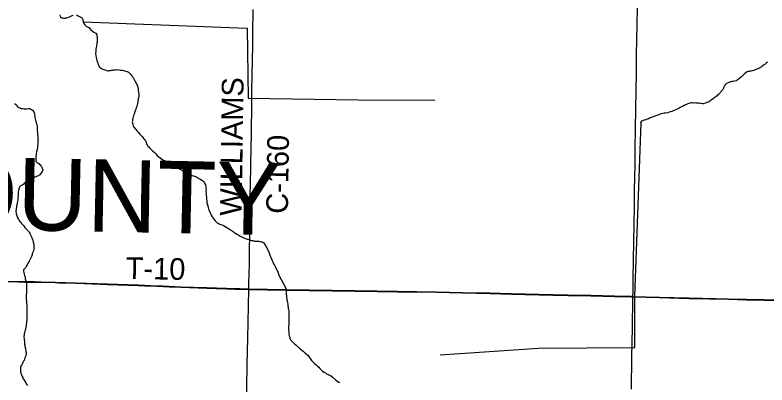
# Model space of a CAD drawing. Extents: x -483 to 680, y 0 to 440.
# Drawn here: x 243.8 to 342.2, y 111.5 to 160 of the extents above; entities that cross this region are included whole.
import ezdxf

# ---------------------------------------------------------------- set-up
doc = ezdxf.new("R2010")
doc.units = 0
for name, color, linetype in [('GM_X_County_Road', 7, 'Continuous'), ('GM_X_County_Road_Text', 7, 'Continuous'), ('GM_X_County_Text', 7, 'Continuous'), ('GM_X_Minor_River', 7, 'Continuous'), ('GM_X_State_Route', 7, 'Continuous'), ('GM_X_Township_Road', 7, 'Continuous'), ('GM_X_Township_Road_Text', 7, 'Continuous'), ('SH_Cut_Line', 7, 'Continuous')]:
    doc.layers.add(name, color=color, linetype=linetype)

msp = doc.modelspace()

# ---------------------------------------------------------------- linework, layer by layer
at = {"layer": 'GM_X_County_Road'}
for points in [[(274.37, 124.047), (274.394, 124.871), (274.43, 126.086), (274.446, 127.389), (274.474, 129.44), (274.494, 130.962), (274.509, 132.174), (274.533, 134.349), (274.567, 136.463), (274.596, 137.83), (274.632, 140.223), (274.683, 142.771), (274.707, 144.231), (274.724, 145.443), (274.751, 147.463), (274.786, 150.167), (274.846, 153.958), (274.889, 156.133), (274.909, 157.625), (274.962, 160.732)], [(273.399, 73.76), (273.41, 74.745), (273.48, 78.087), (273.533, 80.653), (273.585, 83.452), (273.663, 87.183), (273.754, 91.381), (273.896, 97.444), (273.926, 99.154), (273.943, 100.709), (273.972, 102.73), (273.986, 104.13), (274.036, 106.462), (274.073, 108.171), (274.125, 111.216), (274.177, 114.235), (274.24, 117.656), (274.34, 121.854), (274.37, 124.047)]]:
    msp.add_lwpolyline(points, dxfattribs=at)
at = {"layer": 'GM_X_Minor_River'}
for points in [[(249.628, 160.019), (249.679, 159.846), (249.732, 159.711), (249.902, 159.648), (249.996, 159.626), (250.129, 159.622), (250.224, 159.619), (250.338, 159.615), (250.472, 159.629), (250.568, 159.645), (250.762, 159.753), (250.973, 159.822), (251.264, 159.965), (251.399, 160.017)], [(251.799, 160.023), (251.968, 159.96), (252.287, 159.798), (252.473, 159.678), (252.566, 159.598), (252.635, 159.387), (252.67, 159.271), (252.703, 159.118)], [(252.703, 159.118), (274.156, 158.295), (274.281, 149.103), (288.694, 148.911)], [(252.703, 159.118), (252.791, 158.887), (252.899, 158.712), (253.029, 158.594), (253.14, 158.514), (253.234, 158.473), (253.422, 158.372), (253.679, 158.078), (254.069, 157.779), (254.331, 157.638), (254.457, 157.405), (254.472, 157.291), (254.508, 157.194), (254.503, 157.061), (254.516, 156.871), (254.529, 156.68), (254.521, 156.433), (254.478, 156.263), (254.453, 156.093), (254.429, 155.922), (254.404, 155.752), (254.359, 155.525), (254.331, 155.26), (254.322, 154.975), (254.332, 154.689), (254.381, 154.44), (254.432, 154.248), (254.483, 154.037), (254.553, 153.845), (254.623, 153.652), (254.693, 153.46), (254.801, 153.285), (254.91, 153.11), (255.041, 153.03), (255.172, 152.949), (255.379, 152.885), (255.529, 152.823), (255.661, 152.781), (255.774, 152.739), (255.869, 152.717), (255.983, 152.713), (256.098, 152.748), (256.251, 152.761), (256.404, 152.794), (256.557, 152.808), (256.691, 152.823), (256.844, 152.837), (257.015, 152.85), (257.206, 152.863), (257.396, 152.838), (257.585, 152.794), (257.794, 152.768), (257.983, 152.723), (258.549, 152.571), (258.643, 152.53), (258.772, 152.412), (258.845, 152.295), (258.955, 152.178), (259.047, 152.06), (259.12, 151.963), (259.248, 151.806), (259.338, 151.651), (259.41, 151.497), (259.499, 151.323), (259.589, 151.148), (259.661, 151.013), (259.733, 150.877), (259.787, 150.78), (259.82, 150.627), (259.871, 150.454), (259.9, 150.149), (259.948, 149.881), (259.959, 149.633), (259.971, 149.386), (259.945, 149.177), (259.902, 149.027), (259.879, 148.913), (259.855, 148.762), (259.831, 148.591), (259.787, 148.422), (259.743, 148.233), (259.699, 148.044), (259.636, 147.856), (259.613, 147.743), (259.551, 147.592), (259.49, 147.461), (259.448, 147.329), (259.406, 147.198), (259.362, 147.028), (259.299, 146.859), (259.256, 146.689), (259.211, 146.481), (259.167, 146.293), (259.143, 146.122), (259.12, 146.009), (259.135, 145.894), (259.132, 145.799), (259.185, 145.664), (259.237, 145.51), (259.327, 145.336), (259.638, 144.945)], [(342.286, 153.823), (342.113, 153.713), (342.016, 153.639), (341.919, 153.546), (341.822, 153.472), (341.725, 153.398), (341.551, 153.249), (341.435, 153.176), (341.3, 153.103), (341.204, 153.048), (341.05, 152.975), (340.896, 152.921), (340.666, 152.831), (340.493, 152.759), (340.32, 152.706), (340.148, 152.672), (339.976, 152.637), (339.824, 152.622), (339.709, 152.605), (339.613, 152.569), (339.517, 152.514), (339.381, 152.403), (339.303, 152.31), (339.186, 152.198), (339.031, 152.049), (338.876, 151.919), (338.663, 151.753), (338.507, 151.604), (338.391, 151.511), (338.276, 151.476), (338.16, 151.402), (337.95, 151.35), (337.796, 151.296), (337.643, 151.28), (337.51, 151.264), (337.395, 151.248), (337.3, 151.231), (337.126, 151.14), (337.011, 151.085), (336.915, 151.03), (336.798, 150.919), (336.719, 150.806), (336.641, 150.694), (336.581, 150.581), (336.521, 150.449), (336.422, 150.261), (336.305, 150.111), (336.227, 150.018), (336.109, 149.868), (336.031, 149.755), (335.895, 149.644), (335.798, 149.551), (335.681, 149.44), (335.545, 149.328), (335.429, 149.236), (335.333, 149.181), (335.217, 149.088), (334.926, 148.866), (334.791, 148.755), (334.636, 148.644), (334.386, 148.536), (334.137, 148.446), (333.907, 148.394), (333.754, 148.378), (333.603, 148.401), (333.508, 148.422), (333.356, 148.444), (333.166, 148.448), (333.014, 148.471), (332.881, 148.474), (332.71, 148.497), (332.557, 148.481), (332.424, 148.484), (332.272, 148.487), (332.138, 148.452), (332.004, 148.436), (331.851, 148.382), (331.677, 148.291), (331.37, 148.165), (331.158, 148.036), (330.946, 147.927), (330.734, 147.817), (330.542, 147.726), (330.349, 147.616), (330.157, 147.525)], [(288.694, 148.911), (298.75, 148.85)], [(243.678, 148.421), (243.827, 148.321), (243.919, 148.223), (244.029, 148.086), (244.14, 147.987), (244.271, 147.907), (244.421, 147.845), (244.571, 147.783), (244.704, 147.76), (244.799, 147.756), (244.969, 147.713), (245.083, 147.709), (245.216, 147.705), (245.37, 147.738), (245.579, 147.75), (245.713, 147.745), (245.844, 147.684), (245.937, 147.624), (246.05, 147.563), (246.251, 147.309), (246.285, 147.194), (246.32, 147.097), (246.334, 146.926), (246.347, 146.754), (246.38, 146.582), (246.413, 146.41), (246.445, 146.237), (246.478, 146.065), (246.53, 145.911), (246.563, 145.758), (246.615, 145.604), (246.648, 145.432), (246.679, 145.221), (246.669, 144.898), (246.698, 144.612), (246.727, 144.345), (246.739, 144.116), (246.75, 143.849), (246.763, 143.678), (246.779, 143.582), (246.773, 143.373), (246.745, 143.108), (246.719, 142.88), (246.691, 142.615), (246.645, 142.369), (246.578, 142.067), (246.552, 141.84), (246.528, 141.669), (246.503, 141.499), (246.499, 141.366), (246.476, 141.252)], [(330.157, 147.525), (329.946, 147.454), (329.754, 147.363), (329.562, 147.31), (329.39, 147.276), (329.217, 147.204), (328.95, 147.171), (328.759, 147.138), (328.567, 147.104), (328.376, 147.051), (328.223, 147.016), (328.069, 146.944), (327.916, 146.89), (327.781, 146.836), (327.647, 146.801), (327.551, 146.765), (327.417, 146.73), (327.283, 146.675), (327.186, 146.62), (327.071, 146.566), (326.937, 146.531), (326.687, 146.422), (326.533, 146.349), (326.361, 146.296), (326.131, 146.225), (325.997, 146.19), (325.862, 146.136), (325.766, 146.1), (325.707, 145.987), (325.686, 145.93), (325.707, 145.987), (325.686, 145.892)], [(325.686, 145.892), (324.886, 123.142)], [(259.638, 144.945), (259.767, 144.789), (259.913, 144.613), (260.097, 144.417), (260.245, 144.26), (260.392, 144.103), (260.52, 143.946), (260.649, 143.79), (260.758, 143.653), (260.831, 143.536), (260.885, 143.439), (260.938, 143.304), (260.99, 143.151), (261.062, 143.015), (261.151, 142.822), (261.318, 142.702), (261.428, 142.546), (261.594, 142.389), (261.779, 142.211), (261.983, 142.034), (262.186, 141.836), (262.388, 141.621), (262.592, 141.443), (262.759, 141.304), (262.945, 141.165), (263.131, 141.025), (263.412, 140.883), (263.637, 140.78), (263.824, 140.66), (264.01, 140.54), (264.217, 140.457), (264.423, 140.355), (264.685, 140.213), (264.966, 140.052), (265.284, 139.87), (265.546, 139.728), (265.807, 139.567), (266.01, 139.37), (266.273, 139.248), (266.479, 139.146), (266.705, 139.062), (266.932, 138.998), (267.14, 138.953), (267.271, 138.891), (267.384, 138.849), (267.496, 138.789), (267.646, 138.708), (267.795, 138.608), (267.945, 138.527), (268.114, 138.445), (268.319, 138.305), (268.465, 138.129), (268.557, 138.012), (268.629, 137.895), (268.719, 137.74), (268.751, 137.549), (268.767, 137.434), (268.763, 137.32), (268.776, 137.129), (268.769, 136.901), (268.779, 136.635), (268.79, 136.387), (268.821, 136.139), (268.832, 135.891), (268.863, 135.662), (268.892, 135.395), (268.96, 135.145), (269.045, 134.838), (269.114, 134.588), (269.183, 134.377), (269.272, 134.184), (269.361, 133.99), (269.45, 133.778), (269.577, 133.584), (269.723, 133.389), (269.85, 133.194), (269.978, 133.038), (270.107, 132.901), (270.218, 132.783), (270.349, 132.721), (270.48, 132.641), (270.592, 132.58), (270.724, 132.538), (270.856, 132.495), (270.969, 132.454), (271.063, 132.412), (271.157, 132.371), (271.344, 132.27), (271.456, 132.209), (271.624, 132.089), (271.773, 131.989), (271.922, 131.908), (272.053, 131.809), (272.183, 131.729), (272.332, 131.628), (272.463, 131.529), (272.911, 131.248), (273.06, 131.148), (273.246, 131.009), (273.547, 130.904), (273.81, 130.781)], [(246.476, 141.252), (246.473, 141.157), (246.486, 140.967), (246.502, 140.852), (246.63, 140.715), (246.761, 140.615), (246.872, 140.535), (246.983, 140.437), (247.076, 140.358), (247.149, 140.26), (247.222, 140.162), (247.276, 140.046), (247.346, 139.854), (247.417, 139.719), (247.356, 139.587), (247.315, 139.494), (247.254, 139.362), (247.115, 139.196), (247.035, 139.084), (246.919, 139.031), (246.822, 138.958), (246.667, 138.887), (246.513, 138.816), (246.377, 138.745), (246.222, 138.674), (246.048, 138.584), (245.875, 138.533), (245.74, 138.48), (245.625, 138.446), (245.509, 138.412), (245.413, 138.358), (245.235, 138.174), (245.118, 138.063), (244.979, 137.916), (244.862, 137.806), (244.745, 137.733), (244.591, 137.662), (244.494, 137.608), (244.377, 137.536), (244.295, 137.368), (244.273, 137.254), (244.25, 137.122), (244.227, 137.028), (244.184, 136.858), (244.178, 136.687), (244.175, 136.573), (244.171, 136.44), (244.166, 136.307), (244.14, 136.079), (244.133, 135.851), (244.105, 135.586), (244.059, 135.34), (244.015, 135.151), (243.973, 135.02), (243.948, 134.83), (243.921, 134.603), (243.899, 134.489), (243.894, 134.356), (243.891, 134.261), (243.904, 134.071), (243.938, 133.936), (243.989, 133.745), (244.058, 133.514), (244.165, 133.301), (244.258, 133.203), (244.329, 133.068), (244.402, 132.951), (244.512, 132.814), (244.622, 132.696), (244.715, 132.617), (244.825, 132.481), (244.917, 132.401), (245.062, 132.168), (245.246, 131.972), (245.614, 131.56), (245.706, 131.443), (245.758, 131.308), (245.829, 131.135), (245.918, 130.942), (245.989, 130.787), (246.041, 130.614), (246.111, 130.441), (246.162, 130.23), (246.211, 129.981), (246.222, 129.714), (246.233, 129.485), (246.208, 129.296), (246.165, 129.126), (246.124, 129.033), (246.082, 128.939), (246.06, 128.825), (246.019, 128.732), (245.995, 128.58), (245.93, 128.354), (245.789, 128.093), (245.606, 127.737), (245.404, 127.363), (245.282, 127.12), (245.122, 126.897), (245.004, 126.768), (244.885, 126.62)], [(273.81, 130.781), (274.035, 130.697), (274.204, 130.615), (274.336, 130.573), (274.449, 130.531), (274.581, 130.489), (274.733, 130.465), (274.884, 130.441), (275.016, 130.398), (275.13, 130.376), (275.282, 130.371), (275.415, 130.366), (275.568, 130.38), (275.681, 130.358), (275.814, 130.334), (275.984, 130.29), (276.116, 130.267), (276.285, 130.185), (276.396, 130.086), (276.45, 129.99), (276.521, 129.835), (276.631, 129.679), (276.719, 129.467), (276.899, 129.138), (277.023, 128.848), (277.127, 128.541), (277.251, 128.251), (277.374, 127.924), (277.499, 127.653), (277.625, 127.421), (277.732, 127.208), (277.876, 126.956), (278.02, 126.666), (278.18, 126.337), (278.32, 125.933), (279.243, 124.199)], [(244.885, 126.62), (244.898, 126.448), (244.911, 126.257), (244.943, 126.066), (244.995, 125.893), (245.048, 125.777), (245.082, 125.643), (245.097, 125.528), (245.113, 125.433), (245.275, 124.879)], [(245.275, 124.879), (245.284, 124.116), (245.264, 123.888), (245.264, 123.603), (245.244, 123.299), (245.244, 123.09), (245.243, 122.956), (245.243, 122.842), (245.243, 122.728), (245.262, 122.576), (245.261, 122.405), (245.28, 122.215), (245.299, 122.025), (245.298, 121.74), (245.298, 121.588), (245.298, 121.436), (245.297, 121.303), (245.297, 121.188), (245.297, 121.074), (245.297, 120.941), (245.297, 120.789), (245.315, 120.618), (245.315, 120.428), (245.315, 120.219), (245.256, 119.668), (245.237, 119.44), (245.218, 119.25), (245.198, 119.079), (245.16, 118.927), (245.141, 118.813), (245.103, 118.718), (245.083, 118.623), (245.026, 118.452), (244.988, 118.357), (244.969, 118.262), (244.949, 118.129), (244.949, 118.034), (244.93, 117.92), (244.93, 117.787), (244.949, 117.616), (244.967, 117.445), (244.986, 117.293), (245.005, 117.179), (245.004, 117.046), (245.023, 116.893), (245.042, 116.722), (245.061, 116.57), (245.098, 116.418), (245.117, 116.304), (245.155, 116.209), (245.174, 116.057), (245.193, 115.924), (245.211, 115.771), (245.211, 115.619), (245.173, 115.41), (245.134, 115.258), (245.096, 115.163), (245.058, 115.069), (245.02, 114.917), (244.943, 114.746), (244.886, 114.632), (244.81, 114.461), (244.733, 114.347), (244.638, 114.176), (244.562, 114.063), (244.485, 113.835), (244.466, 113.474), (244.465, 113.34), (244.484, 113.207), (244.522, 113.074), (244.56, 112.979), (244.597, 112.865), (244.654, 112.732), (244.711, 112.617), (244.768, 112.503), (244.806, 112.389), (244.882, 112.275), (244.958, 112.142), (245.052, 112.008), (245.128, 111.875), (245.223, 111.685), (245.356, 111.551), (245.431, 111.437)], [(279.243, 124.199), (279.298, 123.03), (279.355, 122.821), (279.374, 122.65), (279.392, 122.498), (279.43, 122.403), (279.449, 122.269), (279.487, 122.117), (279.486, 122.003), (279.505, 121.87), (279.524, 121.737), (279.543, 121.547), (279.58, 121.395), (279.599, 121.243), (279.599, 121.071), (279.618, 120.919), (279.617, 120.729), (279.617, 120.52), (279.597, 120.311), (279.616, 120.178), (279.616, 120.083), (279.616, 119.988), (279.616, 119.874), (279.615, 119.741), (279.615, 119.589), (279.596, 119.418), (279.577, 119.247), (279.576, 119.095), (279.576, 118.924), (279.576, 118.733), (279.594, 118.524), (279.613, 118.315), (279.632, 118.144), (279.669, 117.973), (279.726, 117.783), (279.764, 117.649), (279.802, 117.535), (279.858, 117.44), (279.934, 117.345), (280.048, 117.211), (280.181, 117.097), (280.371, 116.925), (280.561, 116.754), (281.111, 116.239), (281.32, 116.086), (281.51, 115.934), (281.681, 115.781), (281.833, 115.667), (281.984, 115.533), (282.098, 115.419), (282.174, 115.304), (282.269, 115.171), (282.364, 115.019), (282.478, 114.866), (282.592, 114.714), (282.762, 114.561), (282.895, 114.447), (283.028, 114.314), (283.18, 114.161), (283.351, 114.009), (283.522, 113.837), (283.673, 113.665), (283.844, 113.494), (284.034, 113.341), (284.224, 113.208), (284.395, 113.112), (284.547, 112.998), (284.737, 112.921), (284.851, 112.864), (284.965, 112.826), (285.079, 112.749), (285.193, 112.673), (285.307, 112.558), (285.458, 112.444), (285.591, 112.31), (285.724, 112.215), (285.876, 112.101), (286.009, 111.986), (286.142, 111.891), (286.237, 111.852)], [(299.419, 115.474), (312.29, 116.344), (324.905, 116.456), (324.897, 123.142)]]:
    msp.add_lwpolyline(points, dxfattribs=at)
at = {"layer": 'GM_X_State_Route'}
for points in [[(324.667, 123.07), (324.68, 123.838), (324.707, 125.378), (324.783, 130.321), (324.815, 132.559), (324.85, 134.921), (324.884, 137.097), (324.947, 140.329), (324.965, 142.35), (325.013, 145.209), (325.046, 147.603), (325.077, 150.183), (325.115, 152.451), (325.153, 154.783), (325.205, 158.731), (325.246, 160.913)], [(324.464, 110.991), (324.53, 115.185), (324.598, 119.068), (324.662, 122.797), (324.667, 123.07)]]:
    msp.add_lwpolyline(points, dxfattribs=at)
at = {"layer": 'GM_X_Township_Road'}
for points in [[(224.218, 125.28), (225.899, 125.223), (229.529, 125.179), (233.98, 125.126), (238.02, 125.095), (244.236, 125.029), (245.044, 125.018), (246.279, 125), (247.198, 124.985), (249.012, 124.94)], [(249.012, 124.94), (249.061, 124.938), (249.516, 124.925)], [(249.516, 124.925), (251.843, 124.856), (255.883, 124.705), (258.592, 124.607), (259.886, 124.56), (260.718, 124.529), (261.523, 124.501), (262.392, 124.464), (263.147, 124.432), (263.962, 124.397), (265.489, 124.332), (268.897, 124.21), (270.147, 124.18), (270.92, 124.152), (271.462, 124.136), (272.072, 124.117), (272.529, 124.103), (273.222, 124.082), (273.873, 124.062), (274.37, 124.047)], [(274.37, 124.047), (279.235, 123.953), (285.294, 123.871), (291.197, 123.779), (293.838, 123.739), (298.964, 123.667), (302.381, 123.592), (305.954, 123.516), (308.749, 123.441), (314.185, 123.314), (316.205, 123.272), (319.156, 123.216), (322.262, 123.126), (324.436, 123.075), (324.667, 123.07)], [(324.667, 123.07), (328.163, 122.979), (332.046, 122.876), (337.171, 122.753), (339.501, 122.704), (341.831, 122.648), (344.471, 122.582), (345.869, 122.546), (346.789, 122.528), (347.577, 122.512), (349.285, 122.467), (352.547, 122.386), (354.255, 122.352), (355.342, 122.337), (356.117, 122.326), (357.825, 122.293), (358.291, 122.287), (359.376, 122.266), (359.982, 122.245), (360.461, 122.229), (361.606, 122.195), (362.477, 122.169), (366.36, 122.074), (367.515, 122.039)]]:
    msp.add_lwpolyline(points, dxfattribs=at)
at = {"layer": 'SH_Cut_Line'}
for points in [[(344.459, 122.609), (341.819, 122.676), (339.489, 122.732), (337.159, 122.78), (332.034, 122.904), (328.151, 123.007), (324.655, 123.097), (324.424, 123.103), (322.25, 123.154), (319.144, 123.243), (316.193, 123.3), (314.173, 123.342), (308.737, 123.468), (305.942, 123.543), (302.37, 123.62), (298.952, 123.694), (293.826, 123.767), (291.185, 123.807), (285.282, 123.899), (279.224, 123.98), (274.359, 124.075), (273.861, 124.09), (273.21, 124.11), (272.517, 124.131), (272.061, 124.145), (271.45, 124.163), (270.909, 124.18), (270.135, 124.207), (268.885, 124.238), (265.478, 124.359), (263.95, 124.424), (263.136, 124.459), (262.38, 124.491), (261.512, 124.528), (260.707, 124.557), (259.874, 124.587), (258.581, 124.634), (255.871, 124.733), (251.831, 124.883), (249.05, 124.966), (247.186, 125.012), (246.267, 125.027), (245.033, 125.045), (244.224, 125.057), (238.009, 125.123)], [(238.009, 125.123), (244.224, 125.057), (245.033, 125.045), (246.267, 125.027), (247.186, 125.012), (249.05, 124.966), (251.831, 124.883), (255.871, 124.733), (258.581, 124.634), (259.874, 124.587), (260.707, 124.557), (261.512, 124.528), (262.38, 124.491), (263.136, 124.459), (263.95, 124.424), (265.478, 124.359), (268.885, 124.238), (270.135, 124.207), (270.909, 124.18), (271.45, 124.163), (272.061, 124.145), (272.517, 124.131), (273.21, 124.11), (273.861, 124.09), (274.359, 124.075), (279.224, 123.98), (285.282, 123.899), (291.185, 123.807), (293.826, 123.767), (298.952, 123.694), (302.37, 123.62), (305.942, 123.543), (308.737, 123.468), (314.173, 123.342), (316.193, 123.3), (319.144, 123.243), (322.25, 123.154), (324.424, 123.103), (324.655, 123.097), (328.151, 123.007), (332.034, 122.904), (337.159, 122.78), (339.489, 122.732), (341.819, 122.676), (344.459, 122.609)]]:
    msp.add_lwpolyline(points, dxfattribs=at)

# ---------------------------------------------------------------- texts
at = {"layer": 'GM_X_County_Road_Text'}
for s, rotation, p in [('WILLIAMS', 89.17691, (273.439, 133.687)), ('C-160', 89.17368, (279.492, 133.949))]:
    msp.add_text(s, height=2.8409, rotation=rotation, dxfattribs=at).set_placement(p)
at = {"layer": 'GM_X_County_Text'}
msp.add_text('DEFIANCE COUNTY', height=9.4697, rotation=358.83645, dxfattribs=at).set_placement((157.467, 133.6))
at = {"layer": 'GM_X_Township_Road_Text'}
msp.add_text('T-10', height=2.8409, rotation=358.86503, dxfattribs=at).set_placement((258.238, 125.437))

doc.saveas('drawing.dxf')
